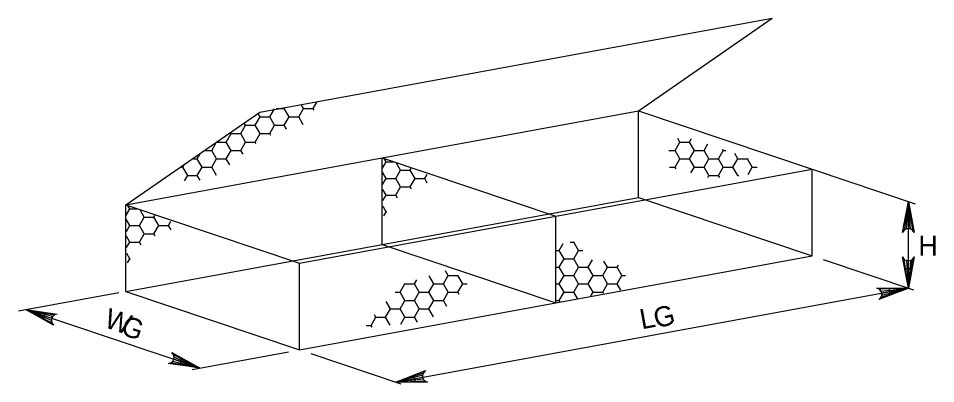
# Model space of a CAD drawing. Extents: x 0 to 36.3, y -44 to 0.
# Drawn here: x 16.43 to 21.91, y -38.15 to -35.97 of the extents above; entities that cross this region are included whole.
import ezdxf

# ---------------------------------------------------------------- set-up
doc = ezdxf.new("R2010")
doc.units = 0
doc.layers.add('3', color=7, linetype='Continuous')
doc.layers.add('5', color=7, linetype='Continuous')

msp = doc.modelspace()

# ---------------------------------------------------------------- linework, layer by layer
at = {"layer": '3'}
for p, q in [((17.8751, -36.5281), (20.9382, -35.9661)), ((20.1385, -36.5199), (20.9382, -35.9661)), ((18.0215, -36.5067), (18.0263, -36.4983)), ((18.1368, -36.5067), (18.1231, -36.4829)), ((18.1945, -36.5067), (18.2169, -36.4679)), ((17.0754, -37.0819), (20.1385, -36.5199)), ((17.0754, -37.0819), (17.8751, -36.5281)), ((17.8485, -36.6066), (17.8773, -36.5567)), ((17.8773, -36.5567), (17.8649, -36.5352)), ((17.8773, -36.5567), (17.935, -36.5567)), ((17.935, -36.5567), (17.9628, -36.5084)), ((17.9638, -36.6066), (17.935, -36.5567)), ((17.9737, -36.5067), (18.0215, -36.5067)), ((18.0503, -36.5567), (18.0215, -36.5067)), ((18.0215, -36.6066), (18.0503, -36.5567)), ((18.0503, -36.5567), (18.108, -36.5567)), ((18.108, -36.5567), (18.1368, -36.5067)), ((18.135, -36.6035), (18.108, -36.5567)), ((18.1368, -36.5067), (18.1945, -36.5067)), ((18.1997, -36.5156), (18.1945, -36.5067)), ((20.1385, -37.0389), (20.1385, -36.5199)), ((20.1385, -36.5199), (21.1766, -36.8689)), ((17.762, -36.6565), (17.7908, -36.6066)), ((17.7908, -36.6066), (17.7828, -36.5928)), ((17.7908, -36.6066), (17.8485, -36.6066)), ((17.8773, -36.6565), (17.8485, -36.6066)), ((17.935, -36.6565), (17.9638, -36.6066)), ((17.9638, -36.6066), (18.0215, -36.6066)), ((18.0346, -36.6292), (18.0215, -36.6066)), ((17.6754, -36.7065), (17.7042, -36.6565)), ((17.7042, -36.6565), (17.7007, -36.6505)), ((17.7042, -36.6565), (17.762, -36.6565)), ((17.7908, -36.7065), (17.762, -36.6565)), ((17.8485, -36.7065), (17.8773, -36.6565)), ((17.8773, -36.6565), (17.935, -36.6565)), ((17.9414, -36.6677), (17.935, -36.6565)), ((17.5889, -36.7564), (17.6156, -36.7103)), ((17.621, -36.7065), (17.6754, -36.7065)), ((17.7042, -36.7564), (17.6754, -36.7065)), ((17.762, -36.7564), (17.7908, -36.7065)), ((17.7908, -36.7065), (17.8485, -36.7065)), ((17.8537, -36.7157), (17.8485, -36.7065)), ((20.3572, -36.7564), (20.386, -36.7065)), ((20.386, -36.7065), (20.374, -36.6857)), ((20.386, -36.7065), (20.4437, -36.7065)), ((20.4437, -36.7065), (20.4563, -36.6847)), ((20.4725, -36.7564), (20.4437, -36.7065)), ((20.5302, -36.7564), (20.5522, -36.7183)), ((17.5024, -36.8063), (17.5186, -36.7783)), ((17.5498, -36.7564), (17.5889, -36.7564)), ((17.6178, -36.8063), (17.5889, -36.7564)), ((17.6754, -36.8063), (17.7042, -36.7564)), ((17.7042, -36.7564), (17.762, -36.7564)), ((17.7754, -36.7798), (17.762, -36.7564)), ((20.3197, -36.7564), (20.3572, -36.7564)), ((20.386, -36.8063), (20.3572, -36.7564)), ((20.4437, -36.8063), (20.4725, -36.7564)), ((20.4725, -36.7564), (20.5302, -36.7564)), ((20.559, -36.8063), (20.5302, -36.7564)), ((20.6167, -36.8063), (20.6455, -36.7564)), ((20.6455, -36.7564), (20.6417, -36.7497)), ((20.6455, -36.7564), (20.6608, -36.7564)), ((20.732, -36.8063), (20.7139, -36.7751)), ((17.4787, -36.8063), (17.5024, -36.8063)), ((17.5312, -36.8563), (17.5024, -36.8063)), ((17.5889, -36.8563), (17.6178, -36.8063)), ((17.6178, -36.8063), (17.6754, -36.8063)), ((17.6968, -36.8434), (17.6754, -36.8063)), ((18.607, -36.8009), (19.6451, -37.1499)), ((18.607, -37.32), (18.607, -36.8009)), ((18.6081, -36.8636), (18.6303, -36.825)), ((18.6303, -36.825), (18.6189, -36.8053)), ((18.6303, -36.825), (18.6722, -36.825)), ((18.7168, -36.875), (18.6922, -36.8325)), ((20.3572, -36.8563), (20.386, -36.8063)), ((20.386, -36.8063), (20.4437, -36.8063)), ((20.4725, -36.8563), (20.4437, -36.8063)), ((20.5302, -36.8563), (20.559, -36.8063)), ((20.559, -36.8063), (20.6167, -36.8063)), ((20.6455, -36.8563), (20.6167, -36.8063)), ((20.7032, -36.8563), (20.732, -36.8063)), ((20.732, -36.8063), (20.7897, -36.8063)), ((20.7897, -36.8063), (20.792, -36.8024)), ((20.8185, -36.8563), (20.7897, -36.8063)), ((17.4076, -36.8563), (17.4159, -36.8563)), ((17.4159, -36.8563), (17.4217, -36.8464)), ((17.4447, -36.9062), (17.4159, -36.8563)), ((17.5024, -36.9062), (17.5312, -36.8563)), ((17.5312, -36.8563), (17.5889, -36.8563)), ((17.6178, -36.9062), (17.5889, -36.8563)), ((18.1135, -37.4309), (21.1766, -36.8689)), ((18.6303, -36.9249), (18.6085, -36.8871)), ((18.688, -36.9249), (18.7168, -36.875)), ((18.7168, -36.875), (18.7745, -36.875)), ((18.7745, -36.875), (18.7802, -36.865)), ((18.8033, -36.9249), (18.7745, -36.875)), ((20.3242, -36.8563), (20.3572, -36.8563)), ((20.3635, -36.8673), (20.3572, -36.8563)), ((20.4523, -36.8912), (20.4725, -36.8563)), ((20.4725, -36.8563), (20.5302, -36.8563)), ((20.559, -36.9062), (20.5302, -36.8563)), ((20.6167, -36.9062), (20.6455, -36.8563)), ((20.6455, -36.8563), (20.7032, -36.8563)), ((20.732, -36.9062), (20.7032, -36.8563)), ((20.7932, -36.9002), (20.8185, -36.8563)), ((20.8185, -36.8563), (20.8485, -36.8563)), ((21.1766, -37.3879), (21.1766, -36.8689)), ((17.4264, -36.9381), (17.4447, -36.9062)), ((17.4447, -36.9062), (17.5024, -36.9062)), ((17.5192, -36.9353), (17.5024, -36.9062)), ((18.6097, -36.9605), (18.6303, -36.9249)), ((18.6303, -36.9249), (18.688, -36.9249)), ((18.7168, -36.9748), (18.688, -36.9249)), ((18.7745, -36.9748), (18.8033, -36.9249)), ((18.8033, -36.9249), (18.861, -36.9249)), ((18.861, -36.9249), (18.8753, -36.9002)), ((18.8767, -36.9522), (18.861, -36.9249)), ((20.5523, -36.918), (20.559, -36.9062)), ((20.559, -36.9062), (20.6167, -36.9062)), ((20.624, -36.919), (20.6167, -36.9062)), ((20.7316, -36.9071), (20.732, -36.9062)), ((20.732, -36.9062), (20.7388, -36.9062)), ((18.6303, -37.0248), (18.6103, -36.9901)), ((18.688, -37.0248), (18.7168, -36.9748)), ((18.7168, -36.9748), (18.7745, -36.9748)), ((18.7826, -36.9889), (18.7745, -36.9748)), ((17.0754, -37.601), (20.1385, -37.0389)), ((18.6114, -37.0575), (18.6303, -37.0248)), ((18.6303, -37.0248), (18.688, -37.0248)), ((18.6988, -37.0436), (18.688, -37.0248)), ((20.1385, -37.0389), (21.1766, -37.3879)), ((17.0754, -37.0819), (18.1135, -37.4309)), ((17.0754, -37.601), (17.0754, -37.0819)), ((17.0765, -37.1446), (17.0987, -37.1061)), ((17.0987, -37.1061), (17.0874, -37.0863)), ((17.0987, -37.1061), (17.1406, -37.1061)), ((18.6303, -37.1247), (18.6121, -37.0931)), ((17.1564, -37.2059), (17.1852, -37.156)), ((17.1852, -37.156), (17.1607, -37.1135)), ((17.1852, -37.156), (17.2429, -37.156)), ((17.2429, -37.156), (17.2487, -37.146)), ((17.2718, -37.2059), (17.2429, -37.156)), ((18.6163, -37.149), (18.6303, -37.1247)), ((18.6303, -37.1247), (18.6353, -37.1247)), ((19.6451, -37.669), (19.6451, -37.1499)), ((17.0987, -37.2059), (17.0769, -37.1682)), ((17.0782, -37.2415), (17.0987, -37.2059)), ((17.0987, -37.2059), (17.1564, -37.2059)), ((17.1852, -37.2558), (17.1564, -37.2059)), ((17.2429, -37.2558), (17.2718, -37.2059)), ((17.2718, -37.2059), (17.3294, -37.2059)), ((17.3294, -37.2059), (17.3438, -37.1812)), ((17.3453, -37.2332), (17.3294, -37.2059)), ((17.0987, -37.3058), (17.0787, -37.2711)), ((17.1564, -37.3058), (17.1852, -37.2558)), ((17.1852, -37.2558), (17.2429, -37.2558)), ((17.251, -37.2699), (17.2429, -37.2558)), ((17.0799, -37.3385), (17.0987, -37.3058)), ((17.0987, -37.3058), (17.1564, -37.3058)), ((17.1672, -37.3246), (17.1564, -37.3058)), ((18.607, -37.32), (19.6451, -37.669)), ((19.6651, -37.3558), (19.6891, -37.3143)), ((19.7311, -37.3058), (19.7516, -37.3058)), ((19.7516, -37.3058), (19.7542, -37.3012)), ((19.7804, -37.3558), (19.7516, -37.3058)), ((17.0987, -37.4057), (17.0805, -37.3741)), ((19.6451, -37.3558), (19.6651, -37.3558)), ((19.6939, -37.4057), (19.6651, -37.3558)), ((19.7516, -37.4057), (19.7804, -37.3558)), ((19.7804, -37.3558), (19.8064, -37.3558)), ((17.0847, -37.43), (17.0987, -37.4057)), ((17.0987, -37.4057), (17.1037, -37.4057)), ((18.1135, -37.95), (21.1766, -37.3879)), ((18.1135, -37.95), (18.1135, -37.4309)), ((19.6651, -37.4557), (19.6939, -37.4057)), ((19.6939, -37.4057), (19.7516, -37.4057)), ((19.7804, -37.4557), (19.7516, -37.4057)), ((19.8381, -37.4557), (19.8636, -37.4115)), ((19.9534, -37.4557), (19.9324, -37.4192)), ((19.0019, -37.5056), (18.9854, -37.4771)), ((19.6451, -37.4557), (19.6651, -37.4557)), ((19.6939, -37.5056), (19.6651, -37.4557)), ((19.7516, -37.5056), (19.7804, -37.4557)), ((19.7804, -37.4557), (19.8381, -37.4557)), ((19.8669, -37.5056), (19.8381, -37.4557)), ((19.9246, -37.5056), (19.9534, -37.4557)), ((19.9534, -37.4557), (20.0112, -37.4557)), ((20.0112, -37.4557), (20.0197, -37.4408)), ((20.04, -37.5056), (20.0112, -37.4557)), ((18.8, -37.5555), (18.814, -37.5314)), ((18.9154, -37.5555), (18.8879, -37.508)), ((18.9731, -37.5555), (19.0019, -37.5056)), ((19.0019, -37.5056), (19.0596, -37.5056)), ((19.0596, -37.5056), (19.0599, -37.505)), ((19.0884, -37.5555), (19.0596, -37.5056)), ((19.6651, -37.5555), (19.6939, -37.5056)), ((19.6939, -37.5056), (19.7516, -37.5056)), ((19.7804, -37.5555), (19.7516, -37.5056)), ((19.8381, -37.5555), (19.8669, -37.5056)), ((19.8669, -37.5056), (19.9246, -37.5056)), ((19.9534, -37.5555), (19.9246, -37.5056)), ((20.0112, -37.5555), (20.04, -37.5056)), ((20.04, -37.5056), (20.0602, -37.5056)), ((17.0754, -37.601), (18.1135, -37.95)), ((18.7135, -37.6055), (18.7423, -37.5555)), ((18.7423, -37.5555), (18.7417, -37.5543)), ((18.7423, -37.5555), (18.8, -37.5555)), ((18.8288, -37.6055), (18.8, -37.5555)), ((18.8866, -37.6055), (18.9154, -37.5555)), ((18.9154, -37.5555), (18.9731, -37.5555)), ((19.0019, -37.6055), (18.9731, -37.5555)), ((19.0596, -37.6055), (19.0884, -37.5555)), ((19.0884, -37.5555), (19.1151, -37.5555)), ((19.6451, -37.5555), (19.6651, -37.5555)), ((19.6939, -37.6055), (19.6651, -37.5555)), ((19.7516, -37.6055), (19.7804, -37.5555)), ((19.7804, -37.5555), (19.8381, -37.5555)), ((19.8669, -37.6055), (19.8381, -37.5555)), ((19.9246, -37.6055), (19.9534, -37.5555)), ((19.9534, -37.5555), (20.0112, -37.5555)), ((20.0328, -37.593), (20.0112, -37.5555)), ((18.685, -37.6055), (18.7135, -37.6055)), ((18.7423, -37.6554), (18.7135, -37.6055)), ((18.7135, -37.7054), (18.7423, -37.6554)), ((18.7423, -37.6554), (18.8, -37.6554)), ((18.8, -37.6554), (18.8288, -37.6055)), ((18.8288, -37.7054), (18.8, -37.6554)), ((18.8288, -37.6055), (18.8866, -37.6055)), ((18.9154, -37.6554), (18.8866, -37.6055)), ((18.8866, -37.7054), (18.9154, -37.6554)), ((18.9154, -37.6554), (18.9731, -37.6554)), ((18.9731, -37.6554), (19.0019, -37.6055)), ((18.9942, -37.692), (18.9731, -37.6554)), ((19.0019, -37.6055), (19.0596, -37.6055)), ((19.0671, -37.6186), (19.0596, -37.6055)), ((19.6451, -37.6554), (19.6651, -37.6554)), ((19.6651, -37.6554), (19.6939, -37.6055)), ((19.6701, -37.6641), (19.6651, -37.6554)), ((19.6939, -37.6055), (19.7516, -37.6055)), ((19.7737, -37.6437), (19.7516, -37.6055)), ((19.8539, -37.628), (19.8669, -37.6055)), ((19.8669, -37.6055), (19.9246, -37.6055)), ((19.9291, -37.6133), (19.9246, -37.6055)), ((18.627, -37.7553), (18.6558, -37.7054)), ((18.6558, -37.7054), (18.63, -37.6605)), ((18.6558, -37.7054), (18.7135, -37.7054)), ((18.7423, -37.7553), (18.7135, -37.7054)), ((18.8, -37.7553), (18.8288, -37.7054)), ((18.8288, -37.7054), (18.8866, -37.7054)), ((18.914, -37.7529), (18.8866, -37.7054)), ((18.5405, -37.8053), (18.5693, -37.7553)), ((18.5693, -37.7553), (18.5607, -37.7403)), ((18.5693, -37.7553), (18.627, -37.7553)), ((18.6548, -37.8035), (18.627, -37.7553)), ((18.7188, -37.7963), (18.7423, -37.7553)), ((18.7423, -37.7553), (18.8, -37.7553)), ((18.8172, -37.7852), (18.8, -37.7553)), ((18.512, -37.8053), (18.5405, -37.8053)), ((18.5466, -37.8158), (18.5405, -37.8053))]:
    msp.add_line(p, q, dxfattribs=at)
at = {"layer": '5'}
for p, q in [((21.1766, -36.8689), (21.7918, -37.0757)), ((21.7516, -37.5812), (21.7516, -37.0622)), ((21.243, -37.4102), (21.7811, -37.5912)), ((18.6885, -38.1433), (21.7516, -37.5812)), ((17.0328, -37.6088), (16.4329, -37.7188)), ((16.478, -37.7098), (17.5161, -38.0588)), ((17.471, -38.0678), (18.0471, -37.9622)), ((18.1799, -37.9723), (18.718, -38.1532))]:
    msp.add_line(p, q, dxfattribs=at)
for points in [[(21.7516, -37.0622), (21.7865, -37.2487), (21.7766, -37.2343), (21.7641, -37.2269), (21.7516, -37.2248), (21.7391, -37.2269), (21.7266, -37.2343), (21.7167, -37.2487), (21.7516, -37.0622), (21.7266, -37.2343), (21.7391, -37.2269), (21.7516, -37.0622), (21.7516, -37.2248), (21.7641, -37.2269), (21.7516, -37.0622), (21.7766, -37.2343)], [(21.7516, -37.5812), (21.7167, -37.3948), (21.7266, -37.4092), (21.7391, -37.4166), (21.7516, -37.4187), (21.7641, -37.4166), (21.7766, -37.4092), (21.7865, -37.3948), (21.7516, -37.5812), (21.7766, -37.4092), (21.7641, -37.4166), (21.7516, -37.5812), (21.7516, -37.4187), (21.7391, -37.4166), (21.7516, -37.5812), (21.7266, -37.4092)], [(21.7516, -37.5812), (21.5745, -37.6493), (21.5868, -37.6369), (21.5919, -37.6232), (21.5917, -37.6106), (21.5874, -37.5987), (21.5778, -37.5877), (21.5619, -37.5805), (21.7516, -37.5812), (21.5778, -37.5877), (21.5874, -37.5987), (21.7516, -37.5812), (21.5917, -37.6106), (21.5919, -37.6232), (21.7516, -37.5812), (21.5868, -37.6369)], [(16.478, -37.7098), (16.6658, -37.7361), (16.6491, -37.741), (16.6381, -37.7504), (16.632, -37.7616), (16.6301, -37.7742), (16.6331, -37.7883), (16.6436, -37.8023), (16.478, -37.7098), (16.6331, -37.7883), (16.6301, -37.7742), (16.478, -37.7098), (16.632, -37.7616), (16.6381, -37.7504), (16.478, -37.7098), (16.6491, -37.741)], [(17.5161, -38.0588), (17.3283, -38.0326), (17.345, -38.0277), (17.356, -38.0183), (17.3621, -38.0071), (17.364, -37.9945), (17.361, -37.9803), (17.3505, -37.9663), (17.5161, -38.0588), (17.361, -37.9803), (17.364, -37.9945), (17.5161, -38.0588), (17.3621, -38.0071), (17.356, -38.0183), (17.5161, -38.0588), (17.345, -38.0277)], [(18.6885, -38.1433), (18.8656, -38.0753), (18.8532, -38.0877), (18.8482, -38.1013), (18.8483, -38.114), (18.8527, -38.1259), (18.8622, -38.1368), (18.8782, -38.1441), (18.6885, -38.1433), (18.8622, -38.1368), (18.8527, -38.1259), (18.6885, -38.1433), (18.8483, -38.114), (18.8482, -38.1013), (18.6885, -38.1433), (18.8532, -38.0877)]]:
    msp.add_lwpolyline(points, dxfattribs=at)
for points in [[(21.7324, -37.1776), (21.7708, -37.1776), (21.7516, -37.0622)], [(21.7708, -37.4659), (21.7324, -37.4659), (21.7516, -37.5812)], [(21.6347, -37.5832), (21.6417, -37.621), (21.7516, -37.5812)], [(16.5826, -37.7654), (16.5948, -37.729), (16.4794, -37.7103)], [(17.3987, -38.0412), (17.411, -38.0048), (17.5141, -38.06)], [(18.8054, -38.1414), (18.7985, -38.1036), (18.6885, -38.1433)]]:
    msp.add_lwpolyline(points, close=True, dxfattribs=at)

# ---------------------------------------------------------------- texts
msp.add_text('H', height=0.12, dxfattribs=at).set_placement((21.8115, -37.387))
for s, rotation, p in [('W', 341.4175, (16.9393, -37.8128)), ('L', 10.3971, (20.1581, -37.8281)), ('G', 15.1898, (20.2472, -37.824)), ('G', 340.7468, (17.0385, -37.8555))]:
    msp.add_text(s, height=0.12, rotation=rotation, dxfattribs=at).set_placement(p)

doc.saveas('drawing.dxf')
